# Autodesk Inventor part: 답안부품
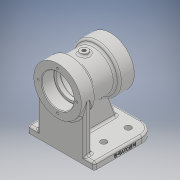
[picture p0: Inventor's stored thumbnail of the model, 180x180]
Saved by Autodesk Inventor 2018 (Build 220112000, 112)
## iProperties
Created: 2020-06
Part Number: 답안부품
Material: 일반
Document SubType Name: Modeling
Designer: USER
Density: 1 g/cm^3
Appearance: 기본값
Mass: 268.662 g
Surface Area: 641.488 cm^2
Volume: 268.662 cm^3
Author: USER
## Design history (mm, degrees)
sketch "스케치1"
  geometry: L1 (-49, -45)-(49, -45); L2 (49, -45)-(49, 45); L3 (49, 45)-(-49, 45); L4 (-49, 45)-(-49, -45); L5 (-49, -45)-(49, 45); L6 (49, -45)-(-49, 45); 1 further point
  constraints: 12 end point, 2 midpoint, 2 parallel, 1 horizontal, 1 perpendicular
  dimensions: "d0" = 98 distance of L3.end L2.end; "d1" = 90 distance of L2.end L1.end
extrude "돌출1" new body sketch "스케치1" distance "d2" = 10; taper "d3" = 0 deg
sketch "스케치2"
  geometry: L1 (-50, 80)-(28, 80); L2 (-50, 80)-(-50, 115); L3 (-50, 115)-(-28, 115); L4 (-28, 115)-(-28, 109); L5 (-28, 109)-(6, 109); L6 (6, 109)-(6, 115); L7 (6, 115)-(28, 115); L8 (28, 115)-(28, 80); L9 (-45, 0)-(45, 0) reference; L10 (-45, 0)-(-45, 10) reference; 1 further point
  constraints: 16 end point, 5 perpendicular, 2 point on line, 1 horizontal, 1 vertical
  dimensions: "d4" = 78 distance of L1.start L1.end; "d5" = 70 diameter of L3 L1; "d6" = 80 distance between parallel lines of L9 L1; "d7" = 5 distance between parallel lines of L2 L10; "d8" = 22 distance of L2.end L3.end; "d9" = 22 distance of L6.end L7.end; "d10" = 58 diameter of L5 L1
revolve "회전1" sketch "스케치2" stored, may be unused: angle "d11" = 90 deg
sketch "스케치3"
  geometry: L1 (-35, -35)-(35, -35); L2 (35, -35)-(35, -45); L3 (35, -45)-(-35, -45); L4 (-35, -45)-(-35, -35); L5 (-49, -45)-(49, -45) reference; 2 further points
  constraints: 8 end point, 2 midpoint, 2 parallel, 1 horizontal, 1 perpendicular
  dimensions: "d12" = 70 distance of L2.end L3.end; "d13" = 10 distance of L1.end L2.end
hole "구멍1" diameter "d16" = 40; stored, may be unused: countersink angle "d20" = 90 deg, drill point angle "d22" = 0 deg; dims "d17" = 6, "d18" = 47, "d19" = 18, "d21" = 24, "d23" = 10, "d24" = 10
hole "구멍2" diameter "d27" = 46; stored, may be unused: countersink angle "d31" = 90 deg, drill point angle "d33" = 0 deg; dims "d25" = 10, "d26" = 10, "d28" = 6, "d29" = 47, "d30" = 18, "d32" = 30
extrude "돌출2" join sketch "스케치3" stored distance "d34" = 10; taper "d35" = 0 deg
sketch "스케치4" dims "d75" = 0.3
  geometry: L1 (45, 10)-(-45, 10) reference; L2 (6, 45)-(6, 115) reference; L3 (28, 45)-(28, 115) reference; L4 (6, 45)-(28, 45) reference; L5 (33, 10)-(20.261, 45); L6 (45, 0)-(45, 10) reference; 1 further point
  constraints: 2 end point, 2 point on line
  dimensions: "d36" = 70 deg angle of L1 L5; "d37" = 12 distance from line of L6 L5.start
feature "리브1" sketch "스케치4" dims "d38" = 1, "d39" = 10, "d40" = 0, "d41" = 0, "d42" = 1, "d43" = 1
sketch "스케치6" dims "d58" = 57
  geometry: C1 r 35 at (0, 0) reference; 3 further points
  constraints: 2 vertical alignment, 3 other
hole "구멍4" sketch "스케치6" at (0, 28.5) diameter "d59" = 3.242; stored, may be unused: countersink angle "d63" = 90 deg, drill point angle "d65" = 118 deg; dims "d60" = 10, "d61" = 47, "d62" = 18, "d64" = 12
node "작업 평면1"
node "작업 평면2"
sketch "스케치5"
  geometry: L1 (5, -28)-(-5, -28) reference; L2 (-5, -28)-(-5, 6) reference; L3 (5, 6)-(-5, 6) reference; L4 (5, 6)-(5, -28) reference; L5 (29, 6)-(-29, 6) reference; L6 (35, -28)-(-35, -28) reference; C1 r 6 at (0, -11); 1 further point
  constraints: 1 centre point, 1 vertical alignment
  dimensions: "d46" = 12 diameter of C1
extrude "돌출3" join sketch "스케치5" stored distance "d47" = 10; taper "d48" = 0 deg
hole "구멍3" diameter "d51" = 5.188; stored, may be unused: countersink angle "d55" = 90 deg, drill point angle "d57" = 0 deg; dims "d49" = 10, "d50" = 10, "d52" = 40, "d53" = 47, "d54" = 18, "d56" = 16
sketch "스케치7"
  geometry: L1 (-14.583, 29.907)-(-14.583, 60.093); L2 (-14.583, 60.093)-(6.583, 60.093); L3 (6.583, 60.093)-(6.583, 29.907); L4 (6.583, 29.907)-(-14.583, 29.907); L5 (-14.583, 45)-(6.583, 45); L6 (-4, 29.907)-(-4, 60.093); L7 (0, 0)-(-10, 0) reference; L8 (0, 0)-(0, 90) reference; 1 further point
  constraints: 4 end point, 4 midpoint, 2 other
  dimensions: "d69" = 45 distance between parallel lines of L5 L7; "d70" = 4 distance between parallel lines of L8 L6
feature "엠보싱1" sketch "스케치7" dims "d0" = 98, "d1" = 90, "d71" = 0.5, "d72" = 0
fillet "모깎기1" dims "d73" = 20
chamfer "모따기1" distance "d76" = 1; stored, may be unused: second distance "d77" = 2, angle "d78" = 45 deg
fillet "모깎기2" dims "d75" = 0.3
fillet "모깎기5" dims "d79" = 3
hole "구멍5" diameter "d82" = 9; stored, may be unused: countersink angle "d86" = 90 deg, drill point angle "d88" = 118 deg; dims "d80" = 10, "d81" = 10, "d83" = 10, "d84" = 47, "d85" = 18, "d87" = 12
node "솔리드1"
pattern_circular "원형 패턴1" dims angle "d67" = 360 deg
mirror "미러1"
fillet "모깎기3" dims "d74" = 3
pattern_linear "직사각형 패턴1" dims "d91" = 36, "d94" = 58
node "투영된 루프1"
node "투영된 루프2"
other parameters: "d44" = -39, "d45" = -112
